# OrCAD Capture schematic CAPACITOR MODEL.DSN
size A4
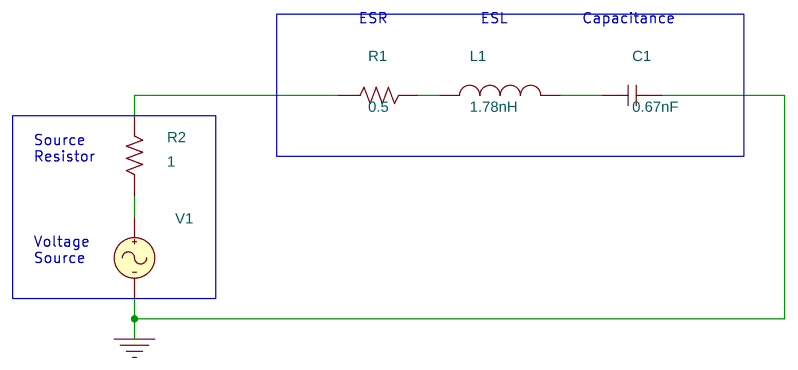
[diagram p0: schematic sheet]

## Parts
C1  0.67nF  [CK05]
L1  1.78nH  [L2012C]
R1  0.5  [RC05]
R2  1  [RC05]
V1  VAC

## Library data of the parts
C1 = C
L1 = L
R1 R2 = R
V1 = VAC

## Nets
0: C1.2 V1.2(-)
N01686: R1.1 R2.2
N04209: C1.1 L1.2
N04220: L1.1 R1.2
N04451: R2.1 V1.1(+)

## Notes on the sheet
- ESR
- ESL
- Capacitance
- Source
  Resistor
- Voltage
  Source
